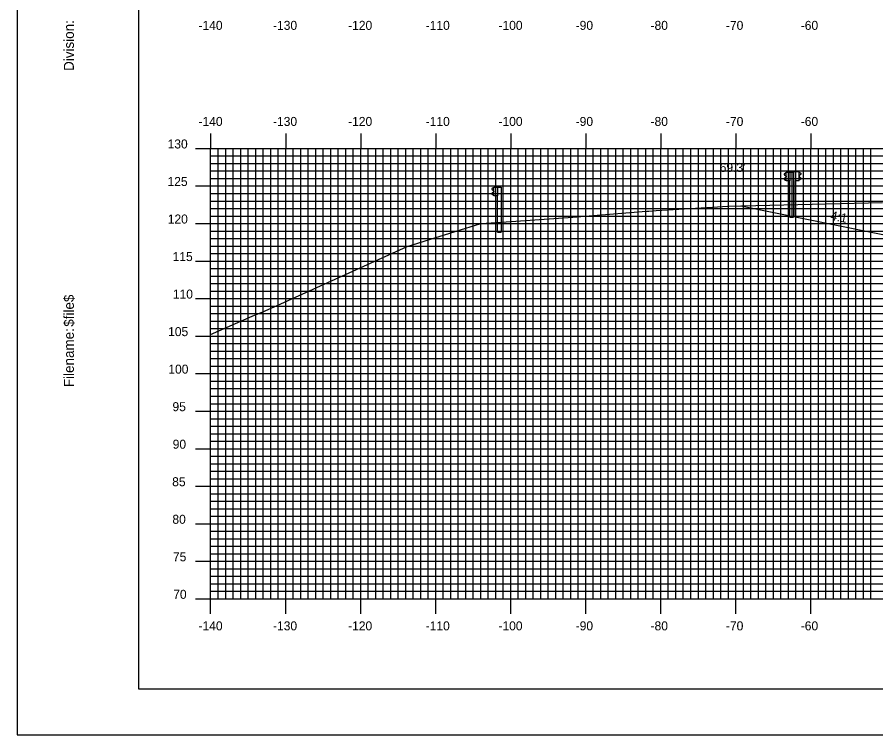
# Model space of a CAD drawing. Extents: x 858684 to 859027, y 364765 to 364985.
# Drawn here: x 858684.1 to 858798.5, y 364765.2 to 364860.8 of the extents above; entities that cross this region are included whole.
import ezdxf

# ---------------------------------------------------------------- set-up
doc = ezdxf.new("R2010")
doc.units = 0
for name, color, linetype in [('ANNOTATION', 7, 'Continuous'), ('BORDER', 7, 'Continuous'), ('D_Roadway_Centerline', 7, 'Continuous'), ('D_Text_Standard', 7, 'Continuous'), ('H_V ANNOTATION', 7, 'Continuous'), ('M_Guardrail', 7, 'Continuous'), ('M_Roadway_Centerline', 7, 'Continuous'), ('MAJOR', 7, 'Continuous'), ('MINOR', 7, 'Continuous'), ('PLOT BOUNDARY', 7, 'Continuous'), ('S_Roadway_Centerline', 7, 'Continuous')]:
    doc.layers.add(name, color=color, linetype=linetype)

msp = doc.modelspace()

# ---------------------------------------------------------------- linework, layer by layer
at = {"layer": 'BORDER'}
msp.add_lwpolyline([(858700.25, 364771.3), (859020.25, 364771.3), (859020.25, 364981.3), (858700.25, 364981.3)], close=True, dxfattribs=at)
at = {"layer": 'D_Roadway_Centerline'}
msp.add_lwpolyline([(858780.52, 364835.65), (858806.92, 364830.35)], dxfattribs=at)
at = {"layer": 'M_Guardrail'}
for p, q in [((858786.47, 364840.04), (858786.32, 364839.94)), ((858786.32, 364839.8), (858786.52, 364839.66)), ((858786.57, 364840.07), (858786.48, 364840.05)), ((858786.57, 364840.14), (858787.06, 364840.14)), ((858786.57, 364838.97), (858786.57, 364840.14)), ((858787.06, 364840.14), (858787.55, 364840.14)), ((858787.06, 364840.14), (858787.06, 364838.97)), ((858787.31, 364840.19), (858787.31, 364834.19)), ((858787.8, 364840.19), (858787.31, 364840.19)), ((858787.55, 364840.14), (858787.55, 364834.14)), ((858788.29, 364840.19), (858787.8, 364840.19)), ((858787.8, 364840.19), (858787.8, 364839.03)), ((858788.29, 364839.03), (858788.29, 364840.19)), ((858788.29, 364840.12), (858788.37, 364840.11)), ((858788.53, 364839.86), (858788.34, 364839.72)), ((858788.39, 364840.1), (858788.53, 364840)), ((858786.52, 364839.44), (858786.32, 364839.31)), ((858786.32, 364839.17), (858786.47, 364839.07)), ((858786.48, 364839.06), (858786.57, 364839.04)), ((858786.55, 364839.6), (858786.55, 364839.51)), ((858787.06, 364838.97), (858786.57, 364838.97)), ((858787.06, 364834.14), (858787.06, 364838.97)), ((858787.8, 364834.19), (858787.8, 364839.03)), ((858787.8, 364839.03), (858788.29, 364839.03)), ((858788.37, 364839.11), (858788.29, 364839.1)), ((858788.3, 364839.66), (858788.3, 364839.57)), ((858788.34, 364839.5), (858788.53, 364839.36)), ((858788.53, 364839.22), (858788.39, 364839.12)), ((858747.51, 364838.07), (858747.36, 364837.97)), ((858747.36, 364837.82), (858747.56, 364837.69)), ((858747.56, 364837.47), (858747.36, 364837.33)), ((858747.61, 364838.09), (858747.52, 364838.07)), ((858747.59, 364837.62), (858747.59, 364837.53)), ((858747.61, 364838.16), (858748.1, 364838.16)), ((858747.61, 364836.99), (858747.61, 364838.16)), ((858748.1, 364838.16), (858748.59, 364838.16)), ((858748.1, 364838.16), (858748.1, 364836.99)), ((858748.59, 364838.16), (858748.59, 364832.16)), ((858747.36, 364837.19), (858747.51, 364837.09)), ((858747.52, 364837.08), (858747.61, 364837.07)), ((858748.1, 364836.99), (858747.61, 364836.99)), ((858748.1, 364832.16), (858748.1, 364836.99)), ((858787.06, 364834.14), (858787.55, 364834.14)), ((858787.8, 364834.19), (858787.31, 364834.19)), ((858748.1, 364832.16), (858748.59, 364832.16))]:
    msp.add_line(p, q, dxfattribs=at)
for centre, major_axis, start_param, end_param in [((858786.37, 364839.87), (-0.0877, 0), 5.323254, 7.243116), ((858786.49, 364840.01), (-0.0417, 0), 4.886922, 5.323254), ((858788.36, 364840.07), (0.0417, 0), 0.959931, 1.396263), ((858788.48, 364839.93), (0.0877, 0), 5.323254, 7.243116), ((858786.37, 364839.24), (-0.0877, 0), 5.323254, 7.243116), ((858786.49, 364839.1), (-0.0417, 0), 0.959931, 1.396263), ((858786.47, 364839.6), (0.0789, 0), 0, 0.959931), ((858786.47, 364839.51), (0.0789, 0), 5.323254, 6.283185), ((858788.38, 364839.66), (-0.0789, 0), 5.323254, 6.283185), ((858788.38, 364839.57), (-0.0789, 0), 6.283185, 7.243116), ((858788.36, 364839.16), (0.0417, 0), 4.886922, 5.323254), ((858788.48, 364839.29), (0.0877, 0), 5.323254, 7.243116), ((858747.41, 364837.89), (-0.0877, 0), 5.323254, 7.243116), ((858747.53, 364838.03), (-0.0417, 0), 4.886922, 5.323254), ((858747.51, 364837.62), (0.0789, 0), 0, 0.959931), ((858747.51, 364837.53), (0.0789, 0), 5.323254, 6.283185), ((858747.41, 364837.26), (-0.0877, 0), 5.323254, 7.243116), ((858747.53, 364837.12), (-0.0417, 0), 0.959931, 1.396263)]:
    msp.add_ellipse(centre, major_axis=major_axis, ratio=0.995501, start_param=start_param, end_param=end_param, dxfattribs=at)
at = {"layer": 'MAJOR'}
for p, q in [((858709.85, 364845.31), (858709.85, 364843.3)), ((858719.85, 364845.31), (858719.85, 364843.3)), ((858729.85, 364845.31), (858729.85, 364843.3)), ((858739.85, 364845.31), (858739.85, 364843.3)), ((858749.85, 364845.31), (858749.85, 364843.3)), ((858759.85, 364845.31), (858759.85, 364843.3)), ((858769.85, 364845.31), (858769.85, 364843.3)), ((858779.85, 364845.31), (858779.85, 364843.3)), ((858789.85, 364845.31), (858789.85, 364843.3)), ((858707.84, 364843.3), (858709.85, 364843.3)), ((858709.85, 364843.3), (858989.85, 364843.3)), ((858709.85, 364783.3), (858709.85, 364843.3)), ((858709.85, 364783.3), (858709.85, 364843.3)), ((858709.85, 364843.3), (858989.85, 364843.3)), ((858719.85, 364783.3), (858719.85, 364843.3)), ((858729.85, 364783.3), (858729.85, 364843.3)), ((858739.85, 364783.3), (858739.85, 364843.3)), ((858749.85, 364783.3), (858749.85, 364843.3)), ((858759.85, 364783.3), (858759.85, 364843.3)), ((858769.85, 364783.3), (858769.85, 364843.3)), ((858779.85, 364783.3), (858779.85, 364843.3)), ((858789.85, 364783.3), (858789.85, 364843.3)), ((858707.84, 364838.3), (858709.85, 364838.3)), ((858709.85, 364838.3), (858989.85, 364838.3)), ((858707.84, 364833.3), (858709.85, 364833.3)), ((858709.85, 364833.3), (858989.85, 364833.3)), ((858707.84, 364828.3), (858709.85, 364828.3)), ((858709.85, 364828.3), (858989.85, 364828.3)), ((858707.84, 364823.3), (858709.85, 364823.3)), ((858709.85, 364823.3), (858989.85, 364823.3)), ((858707.84, 364818.3), (858709.85, 364818.3)), ((858709.85, 364818.3), (858989.85, 364818.3)), ((858707.84, 364813.3), (858709.85, 364813.3)), ((858709.85, 364813.3), (858989.85, 364813.3)), ((858707.84, 364808.3), (858709.85, 364808.3)), ((858709.85, 364808.3), (858989.85, 364808.3)), ((858707.84, 364803.3), (858709.85, 364803.3)), ((858709.85, 364803.3), (858989.85, 364803.3)), ((858707.84, 364798.3), (858709.85, 364798.3)), ((858709.85, 364798.3), (858989.85, 364798.3)), ((858707.84, 364793.3), (858709.85, 364793.3)), ((858709.85, 364793.3), (858989.85, 364793.3)), ((858707.84, 364788.3), (858709.85, 364788.3)), ((858709.85, 364788.3), (858989.85, 364788.3)), ((858707.84, 364783.3), (858709.85, 364783.3)), ((858709.85, 364783.3), (858989.85, 364783.3)), ((858709.85, 364783.3), (858989.85, 364783.3)), ((858709.85, 364781.3), (858709.85, 364783.3)), ((858719.85, 364781.3), (858719.85, 364783.3)), ((858729.85, 364781.3), (858729.85, 364783.3)), ((858739.85, 364781.3), (858739.85, 364783.3)), ((858749.85, 364781.3), (858749.85, 364783.3)), ((858759.85, 364781.3), (858759.85, 364783.3)), ((858769.85, 364781.3), (858769.85, 364783.3)), ((858779.85, 364781.3), (858779.85, 364783.3)), ((858789.85, 364781.3), (858789.85, 364783.3))]:
    msp.add_line(p, q, dxfattribs=at)
at = {"layer": 'MINOR'}
for p, q in [((858710.85, 364783.3), (858710.85, 364843.3)), ((858711.85, 364783.3), (858711.85, 364843.3)), ((858712.85, 364783.3), (858712.85, 364843.3)), ((858713.85, 364783.3), (858713.85, 364843.3)), ((858714.85, 364783.3), (858714.85, 364843.3)), ((858715.85, 364783.3), (858715.85, 364843.3)), ((858716.85, 364783.3), (858716.85, 364843.3)), ((858717.85, 364783.3), (858717.85, 364843.3)), ((858718.85, 364783.3), (858718.85, 364843.3)), ((858720.85, 364783.3), (858720.85, 364843.3)), ((858721.85, 364783.3), (858721.85, 364843.3)), ((858722.85, 364783.3), (858722.85, 364843.3)), ((858723.85, 364783.3), (858723.85, 364843.3)), ((858724.85, 364783.3), (858724.85, 364843.3)), ((858725.85, 364783.3), (858725.85, 364843.3)), ((858726.85, 364783.3), (858726.85, 364843.3)), ((858727.85, 364783.3), (858727.85, 364843.3)), ((858728.85, 364783.3), (858728.85, 364843.3)), ((858730.85, 364783.3), (858730.85, 364843.3)), ((858731.85, 364783.3), (858731.85, 364843.3)), ((858732.85, 364783.3), (858732.85, 364843.3)), ((858733.85, 364783.3), (858733.85, 364843.3)), ((858734.85, 364783.3), (858734.85, 364843.3)), ((858735.85, 364783.3), (858735.85, 364843.3)), ((858736.85, 364783.3), (858736.85, 364843.3)), ((858737.85, 364783.3), (858737.85, 364843.3)), ((858738.85, 364783.3), (858738.85, 364843.3)), ((858740.85, 364783.3), (858740.85, 364843.3)), ((858741.85, 364783.3), (858741.85, 364843.3)), ((858742.85, 364783.3), (858742.85, 364843.3)), ((858743.85, 364783.3), (858743.85, 364843.3)), ((858744.85, 364783.3), (858744.85, 364843.3)), ((858745.85, 364783.3), (858745.85, 364843.3)), ((858746.85, 364783.3), (858746.85, 364843.3)), ((858747.85, 364783.3), (858747.85, 364843.3)), ((858748.85, 364783.3), (858748.85, 364843.3)), ((858750.85, 364783.3), (858750.85, 364843.3)), ((858751.85, 364783.3), (858751.85, 364843.3)), ((858752.85, 364783.3), (858752.85, 364843.3)), ((858753.85, 364783.3), (858753.85, 364843.3)), ((858754.85, 364783.3), (858754.85, 364843.3)), ((858755.85, 364783.3), (858755.85, 364843.3)), ((858756.85, 364783.3), (858756.85, 364843.3)), ((858757.85, 364783.3), (858757.85, 364843.3)), ((858758.85, 364783.3), (858758.85, 364843.3)), ((858760.85, 364783.3), (858760.85, 364843.3)), ((858761.85, 364783.3), (858761.85, 364843.3)), ((858762.85, 364783.3), (858762.85, 364843.3)), ((858763.85, 364783.3), (858763.85, 364843.3)), ((858764.85, 364783.3), (858764.85, 364843.3)), ((858765.85, 364783.3), (858765.85, 364843.3)), ((858766.85, 364783.3), (858766.85, 364843.3)), ((858767.85, 364783.3), (858767.85, 364843.3)), ((858768.85, 364783.3), (858768.85, 364843.3)), ((858770.85, 364783.3), (858770.85, 364843.3)), ((858771.85, 364783.3), (858771.85, 364843.3)), ((858772.85, 364783.3), (858772.85, 364843.3)), ((858773.85, 364783.3), (858773.85, 364843.3)), ((858774.85, 364783.3), (858774.85, 364843.3)), ((858775.85, 364783.3), (858775.85, 364843.3)), ((858776.85, 364783.3), (858776.85, 364843.3)), ((858777.85, 364783.3), (858777.85, 364843.3)), ((858778.85, 364783.3), (858778.85, 364843.3)), ((858780.85, 364783.3), (858780.85, 364843.3)), ((858781.85, 364783.3), (858781.85, 364843.3)), ((858782.85, 364783.3), (858782.85, 364843.3)), ((858783.85, 364783.3), (858783.85, 364843.3)), ((858784.85, 364783.3), (858784.85, 364843.3)), ((858785.85, 364783.3), (858785.85, 364843.3)), ((858786.85, 364783.3), (858786.85, 364843.3)), ((858787.85, 364783.3), (858787.85, 364843.3)), ((858788.85, 364783.3), (858788.85, 364843.3)), ((858790.85, 364783.3), (858790.85, 364843.3)), ((858791.85, 364783.3), (858791.85, 364843.3)), ((858792.85, 364783.3), (858792.85, 364843.3)), ((858793.85, 364783.3), (858793.85, 364843.3)), ((858794.85, 364783.3), (858794.85, 364843.3)), ((858795.85, 364783.3), (858795.85, 364843.3)), ((858796.85, 364783.3), (858796.85, 364843.3)), ((858797.85, 364783.3), (858797.85, 364843.3)), ((858709.85, 364842.3), (858989.85, 364842.3)), ((858709.85, 364842.3), (858711.85, 364842.3)), ((858709.85, 364841.3), (858989.85, 364841.3)), ((858709.85, 364841.3), (858711.85, 364841.3)), ((858709.85, 364840.3), (858989.85, 364840.3)), ((858709.85, 364840.3), (858711.85, 364840.3)), ((858709.85, 364839.3), (858989.85, 364839.3)), ((858709.85, 364839.3), (858711.85, 364839.3)), ((858709.85, 364837.3), (858989.85, 364837.3)), ((858709.85, 364837.3), (858711.85, 364837.3)), ((858709.85, 364836.3), (858989.85, 364836.3)), ((858709.85, 364836.3), (858711.85, 364836.3)), ((858709.85, 364835.3), (858989.85, 364835.3)), ((858709.85, 364835.3), (858711.85, 364835.3)), ((858709.85, 364834.3), (858989.85, 364834.3)), ((858709.85, 364834.3), (858711.85, 364834.3)), ((858709.85, 364832.3), (858989.85, 364832.3)), ((858709.85, 364832.3), (858711.85, 364832.3)), ((858709.85, 364831.3), (858989.85, 364831.3)), ((858709.85, 364831.3), (858711.85, 364831.3)), ((858709.85, 364830.3), (858989.85, 364830.3)), ((858709.85, 364830.3), (858711.85, 364830.3)), ((858709.85, 364829.3), (858989.85, 364829.3)), ((858709.85, 364829.3), (858711.85, 364829.3)), ((858709.85, 364827.3), (858989.85, 364827.3)), ((858709.85, 364827.3), (858711.85, 364827.3)), ((858709.85, 364826.3), (858989.85, 364826.3)), ((858709.85, 364826.3), (858711.85, 364826.3)), ((858709.85, 364825.3), (858989.85, 364825.3)), ((858709.85, 364825.3), (858711.85, 364825.3)), ((858709.85, 364824.3), (858989.85, 364824.3)), ((858709.85, 364824.3), (858711.85, 364824.3)), ((858709.85, 364822.3), (858989.85, 364822.3)), ((858709.85, 364822.3), (858711.85, 364822.3)), ((858709.85, 364821.3), (858989.85, 364821.3)), ((858709.85, 364821.3), (858711.85, 364821.3)), ((858709.85, 364820.3), (858989.85, 364820.3)), ((858709.85, 364820.3), (858711.85, 364820.3)), ((858709.85, 364819.3), (858989.85, 364819.3)), ((858709.85, 364819.3), (858711.85, 364819.3)), ((858709.85, 364817.3), (858989.85, 364817.3)), ((858709.85, 364817.3), (858711.85, 364817.3)), ((858709.85, 364816.3), (858989.85, 364816.3)), ((858709.85, 364816.3), (858711.85, 364816.3)), ((858709.85, 364815.3), (858989.85, 364815.3)), ((858709.85, 364815.3), (858711.85, 364815.3)), ((858709.85, 364814.3), (858989.85, 364814.3)), ((858709.85, 364814.3), (858711.85, 364814.3)), ((858709.85, 364812.3), (858989.85, 364812.3)), ((858709.85, 364812.3), (858711.85, 364812.3)), ((858709.85, 364811.3), (858989.85, 364811.3)), ((858709.85, 364811.3), (858711.85, 364811.3)), ((858709.85, 364810.3), (858989.85, 364810.3)), ((858709.85, 364810.3), (858711.85, 364810.3)), ((858709.85, 364809.3), (858989.85, 364809.3)), ((858709.85, 364809.3), (858711.85, 364809.3)), ((858709.85, 364807.3), (858989.85, 364807.3)), ((858709.85, 364807.3), (858711.85, 364807.3)), ((858709.85, 364806.3), (858989.85, 364806.3)), ((858709.85, 364806.3), (858711.85, 364806.3)), ((858709.85, 364805.3), (858989.85, 364805.3)), ((858709.85, 364805.3), (858711.85, 364805.3)), ((858709.85, 364804.3), (858989.85, 364804.3)), ((858709.85, 364804.3), (858711.85, 364804.3)), ((858709.85, 364802.3), (858989.85, 364802.3)), ((858709.85, 364802.3), (858711.85, 364802.3)), ((858709.85, 364801.3), (858989.85, 364801.3)), ((858709.85, 364801.3), (858711.85, 364801.3)), ((858709.85, 364800.3), (858989.85, 364800.3)), ((858709.85, 364800.3), (858711.85, 364800.3)), ((858709.85, 364799.3), (858989.85, 364799.3)), ((858709.85, 364799.3), (858711.85, 364799.3)), ((858709.85, 364797.3), (858989.85, 364797.3)), ((858709.85, 364797.3), (858711.85, 364797.3)), ((858709.85, 364796.3), (858989.85, 364796.3)), ((858709.85, 364796.3), (858711.85, 364796.3)), ((858709.85, 364795.3), (858989.85, 364795.3)), ((858709.85, 364795.3), (858711.85, 364795.3)), ((858709.85, 364794.3), (858989.85, 364794.3)), ((858709.85, 364794.3), (858711.85, 364794.3)), ((858709.85, 364792.3), (858989.85, 364792.3)), ((858709.85, 364792.3), (858711.85, 364792.3)), ((858709.85, 364791.3), (858989.85, 364791.3)), ((858709.85, 364791.3), (858711.85, 364791.3)), ((858709.85, 364790.3), (858989.85, 364790.3)), ((858709.85, 364790.3), (858711.85, 364790.3)), ((858709.85, 364789.3), (858989.85, 364789.3)), ((858709.85, 364789.3), (858711.85, 364789.3)), ((858709.85, 364787.3), (858989.85, 364787.3)), ((858709.85, 364787.3), (858711.85, 364787.3)), ((858709.85, 364786.3), (858989.85, 364786.3)), ((858709.85, 364786.3), (858711.85, 364786.3)), ((858709.85, 364785.3), (858989.85, 364785.3)), ((858709.85, 364785.3), (858711.85, 364785.3)), ((858709.85, 364784.3), (858989.85, 364784.3)), ((858709.85, 364784.3), (858711.85, 364784.3))]:
    msp.add_line(p, q, dxfattribs=at)
at = {"layer": 'PLOT BOUNDARY'}
msp.add_lwpolyline([(858684.06, 364765.18), (859024.06, 364765.18), (859024.06, 364985.18), (858684.06, 364985.18)], close=True, dxfattribs=at)
at = {"layer": 'S_Roadway_Centerline'}
msp.add_lwpolyline([(858709.85, 364818.5), (858715.36, 364820.96), (858716.79, 364821.52), (858718.72, 364822.37), (858736.04, 364830.24), (858739, 364831.17), (858745.84, 364833.31), (858748.61, 364833.5), (858758.13, 364834.15), (858767.37, 364834.9), (858768.04, 364834.95), (858768.24, 364834.96), (858769.24, 364835.02), (858776.73, 364835.5), (858778.73, 364835.61), (858799.39, 364836.12)], dxfattribs=at)

# ---------------------------------------------------------------- texts
at = {"layer": 'ANNOTATION'}
msp.add_text('4:1', height=1.2, rotation=348.6438, dxfattribs=at).set_placement((858792.38, 364833.82))
at = {"layer": 'BORDER'}
for s, p in [('Division:', (858691.62, 364853.63)), ('$file$', (858691.62, 364819.55)), ('Filename:', (858691.62, 364811.5))]:
    msp.add_text(s, height=1.339, rotation=90, dxfattribs=at).set_placement(p)
at = {"layer": 'D_Text_Standard'}
msp.add_text("69.3'", height=1.2, dxfattribs=at).set_placement((858777.7, 364840.17))
at = {"layer": 'H_V ANNOTATION'}
for s, p in [('-140', (858708.23, 364859.1)), ('-130', (858718.16, 364859.1)), ('-120', (858728.17, 364859.1)), ('-110', (858738.51, 364859.1)), ('-100', (858748.21, 364859.1)), ('-90', (858758.5, 364859.1)), ('-80', (858768.48, 364859.1)), ('-70', (858778.53, 364859.1)), ('-60', (858788.5, 364859.1)), ('-140', (858708.23, 364846.3)), ('-130', (858718.16, 364846.3)), ('-120', (858728.17, 364846.3)), ('-110', (858738.51, 364846.3)), ('-100', (858748.21, 364846.3)), ('-90', (858758.5, 364846.3)), ('-80', (858768.48, 364846.3)), ('-70', (858778.53, 364846.3)), ('-60', (858788.5, 364846.3)), ('130', (858704.11, 364843.3)), ('125', (858704.1, 364838.3)), ('120', (858704.13, 364833.3)), ('115', (858704.78, 364828.3)), ('110', (858704.81, 364823.3)), ('105', (858704.18, 364818.3)), ('100', (858704.21, 364813.3)), ('95', (858704.76, 364808.3)), ('90', (858704.79, 364803.3)), ('85', (858704.72, 364798.3)), ('80', (858704.75, 364793.3)), ('75', (858704.82, 364788.3)), ('70', (858704.86, 364783.3)), ('-140', (858708.23, 364779.1)), ('-130', (858718.16, 364779.1)), ('-120', (858728.17, 364779.1)), ('-110', (858738.51, 364779.1)), ('-100', (858748.21, 364779.1)), ('-90', (858758.5, 364779.1)), ('-80', (858768.48, 364779.1)), ('-70', (858778.53, 364779.1)), ('-60', (858788.5, 364779.1))]:
    msp.add_text(s, height=1.2, dxfattribs=at).set_placement(p)
at = {"layer": 'M_Roadway_Centerline'}
for s, p in [('C', (858768.03, 364834.95)), ('L', (858768.04, 364834.94))]:
    msp.add_text(s, height=0.0146, dxfattribs=at).set_placement(p)
at = {"layer": 'MAJOR'}
msp.add_text('-', height=0.012, dxfattribs=at).set_placement((858709.84, 364783.3))

doc.saveas('drawing.dxf')
